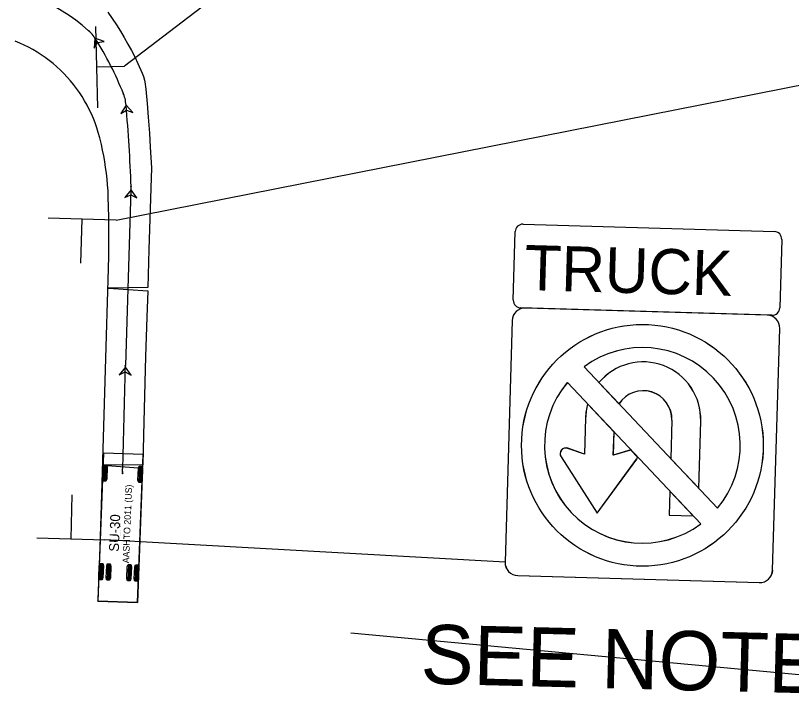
# Model space of a CAD drawing. Extents: x 2096670 to 2098561, y 684033 to 689893.
# Drawn here: x 2097702.4 to 2097859.5, y 686753.6 to 686892.9 of the extents above; entities that cross this region are included whole.
import ezdxf

# ---------------------------------------------------------------- set-up
doc = ezdxf.new("R2010")
doc.units = 0
for name, color, linetype in [('Exist Sign E No U Turn CELL', 7, 'Continuous'), ('Exist Sign E Two Direction', 7, 'Continuous'), ('Exist Support 1', 7, 'Continuous'), ('Old_Level_63', 7, 'Continuous'), ('Prop DSN Text', 7, 'Continuous'), ('Prop Sign E One Way_Right CELL', 7, 'Continuous'), ('Prop Sign E Signal Light Ahead CELL', 7, 'Continuous'), ('Scratch_Level_3', 7, 'Continuous')]:
    doc.layers.add(name, color=color, linetype=linetype)

# ---------------------------------------------------------------- blocks, each defined once
blk = doc.blocks.new('Exist No U Turn')
at = {"layer": 'Exist Sign E No U Turn CELL'}
for p, q in [((56.27, 62.3), (-56.61, 62.3)), ((-62.66, 56.26), (-62.66, -56.62)), ((62.31, -56.62), (62.31, 56.26)), ((-28.46, 35.7), (35.71, -28.46)), ((-28.46, 35.7), (-28.46, 35.7)), ((-36.06, 28.1), (28.11, -36.06)), ((-36.06, 28.1), (-36.06, 28.1)), ((-21.29, 28.54), (-11.65, 18.9)), ((-21.29, 28.54), (-11.65, 18.9)), ((-21.29, 28.54), (-11.65, 18.9)), ((-11.65, 18.9), (-11.65, 18.9)), ((-11.65, 18.9), (-11.65, 18.9)), ((-11.65, 18.9), (-11.65, 18.9)), ((-2.25, -5.71), (-5.43, -2.52)), ((-2.67, -6.68), (-2.67, -6.68)), ((-2.67, -6.68), (-2.67, -6.68)), ((-56.61, -62.67), (56.27, -62.67))]:
    blk.add_line(p, q, dxfattribs=at)
for points in [[(-2.25, -5.71), (-5.45, -2.51), (-13.61, -5.1), (-13.61, 5.66), (-26.27, 18.32)], [(-5.72, -2.6), (-13.61, -5.1), (-13.61, 5.66), (-26.27, 18.32)], [(-2.25, -5.71), (-5.45, -2.51), (-13.61, -5.1), (-13.61, 5.66), (-26.27, 18.32)], [(-27.05, 11.91), (-27.05, -5.1), (-34.96, -2.59)], [(-27.05, 11.91), (-27.05, -5.1), (-34.96, -2.59)], [(-27.05, 11.91), (-27.05, -5.1), (-34.96, -2.59)], [(13.27, 11.91), (13.27, -6.02), (26.7, -19.46), (26.7, 11.91)], [(13.27, 11.91), (13.27, -6.02), (26.7, -19.46), (26.7, 11.91)], [(13.27, 11.91), (13.27, -6.02), (26.7, -19.46), (26.7, 11.91)], [(-38, -6.67), (-20.33, -32.43), (-2.67, -6.68)], [(-38, -6.67), (-20.33, -32.43), (-2.67, -6.68)], [(-38, -6.67), (-20.33, -32.43), (-2.67, -6.68)]]:
    blk.add_lwpolyline(points, dxfattribs=at)
blk.add_lwpolyline([(13.27, -21.22), (13.27, -32.43), (24.48, -32.43)], close=True, dxfattribs=at)
blk.add_lwpolyline([(13.27, -21.22), (13.27, -32.43), (24.48, -32.43)], close=True, dxfattribs=at)
blk.add_lwpolyline([(13.27, -21.22), (13.27, -32.43), (24.48, -32.43)], close=True, dxfattribs=at)
blk.add_circle((-0.17, -0.18), 56.44, dxfattribs=at)
for centre, radius, start, end in [((-56.61, 56.26), 6.05, 90, 180), ((56.27, 56.26), 6.05, 0, 90), ((-0.17, -0.18), 45.69, 321.7553, 128.2447), ((-0.17, 11.91), 26.88, 359.9928, 141.788), ((-0.17, 11.91), 26.88, 359.9928, 141.788), ((-0.17, 11.91), 26.88, 359.9928, 141.788), ((-0.17, -0.18), 45.69, 141.7553, 308.2447), ((-0.17, 11.91), 13.44, 0, 148.6739), ((-0.17, 11.91), 13.44, 0, 148.6739), ((-0.17, 11.91), 13.44, 0, 148.6739), ((-0.17, 11.91), 26.87, 166.2094, 180), ((-0.17, 11.91), 26.87, 166.2094, 180), ((-0.17, 11.91), 26.87, 166.2094, 180), ((-35.78, -5.15), 2.69, 72.3746, 214.4704), ((-35.78, -5.15), 2.69, 72.3746, 214.4704), ((-35.78, -5.15), 2.69, 72.3746, 214.4704), ((-4.9, -5.14), 2.67, 101.5336, 108.0305), ((-4.9, -5.14), 2.67, 101.5336, 107.1991), ((-4.9, -5.14), 2.67, 101.5336, 107.1991), ((-4.88, -5.15), 2.69, 325.4527, 348.1626), ((-4.88, -5.15), 2.69, 325.4527, 348.1626), ((-4.88, -5.15), 2.69, 325.4527, 348.1626), ((-56.61, -56.62), 6.05, 180, 270), ((56.27, -56.62), 6.05, 270, 0)]:
    blk.add_arc(centre, radius, start, end, dxfattribs=at)

msp = doc.modelspace()

# ---------------------------------------------------------------- linework, layer by layer
at = {"layer": 'Exist Sign E No U Turn CELL'}
for p, q in [((2097805.19, 686850.68), (2097856.07, 686849.2)), ((2097803.2, 686835.31), (2097803.6, 686849.18)), ((2097857.57, 686847.61), (2097857.17, 686833.74)), ((2097855.58, 686832.24), (2097804.7, 686833.72)), ((2097854.6, 686832.27), (2097805.67, 686833.69)), ((2097802.97, 686831.15), (2097801.55, 686782.21)), ((2097855.73, 686780.64), (2097857.15, 686829.57)), ((2097817.54, 686821.8), (2097844.55, 686793.18)), ((2097817.54, 686821.8), (2097817.54, 686821.8)), ((2097814.15, 686818.6), (2097841.16, 686789.98)), ((2097814.15, 686818.6), (2097814.15, 686818.6)), ((2097820.56, 686818.61), (2097824.61, 686814.31)), ((2097820.56, 686818.61), (2097824.61, 686814.31)), ((2097820.56, 686818.61), (2097824.61, 686814.31)), ((2097824.61, 686814.31), (2097824.61, 686814.31)), ((2097824.61, 686814.31), (2097824.61, 686814.31)), ((2097824.61, 686814.31), (2097824.61, 686814.31)), ((2097828.38, 686803.52), (2097827.04, 686804.94)), ((2097828.19, 686803.1), (2097828.19, 686803.1)), ((2097828.19, 686803.1), (2097828.19, 686803.1)), ((2097801.55, 686782.21), (2097720.47, 686786.74)), ((2097804.09, 686779.51), (2097853.03, 686778.09))]:
    msp.add_line(p, q, dxfattribs=at)
for points in [[(2097828.38, 686803.52), (2097827.03, 686804.95), (2097823.46, 686803.93), (2097823.6, 686808.59), (2097818.27, 686814.24)], [(2097826.91, 686804.91), (2097823.46, 686803.93), (2097823.6, 686808.59), (2097818.27, 686814.24)], [(2097828.38, 686803.52), (2097827.03, 686804.95), (2097823.46, 686803.93), (2097823.6, 686808.59), (2097818.27, 686814.24)], [(2097817.85, 686811.47), (2097817.64, 686804.09), (2097814.24, 686805.28)], [(2097817.85, 686811.47), (2097817.64, 686804.09), (2097814.24, 686805.28)], [(2097817.85, 686811.47), (2097817.64, 686804.09), (2097814.24, 686805.28)], [(2097835.33, 686810.96), (2097835.1, 686803.19), (2097840.76, 686797.2), (2097841.15, 686810.79)], [(2097835.33, 686810.96), (2097835.1, 686803.19), (2097840.76, 686797.2), (2097841.15, 686810.79)], [(2097835.33, 686810.96), (2097835.1, 686803.19), (2097840.76, 686797.2), (2097841.15, 686810.79)], [(2097812.87, 686803.55), (2097820.2, 686792.16), (2097828.19, 686803.1)], [(2097812.87, 686803.55), (2097820.2, 686792.16), (2097828.19, 686803.1)], [(2097812.87, 686803.55), (2097820.2, 686792.16), (2097828.19, 686803.1)]]:
    msp.add_lwpolyline(points, dxfattribs=at)
msp.add_lwpolyline([(2097834.91, 686796.6), (2097834.77, 686791.74), (2097839.63, 686791.6)], close=True, dxfattribs=at)
msp.add_lwpolyline([(2097834.91, 686796.6), (2097834.77, 686791.74), (2097839.63, 686791.6)], close=True, dxfattribs=at)
msp.add_lwpolyline([(2097834.91, 686796.6), (2097834.77, 686791.74), (2097839.63, 686791.6)], close=True, dxfattribs=at)
msp.add_circle((2097829.35, 686805.89), 24.48, dxfattribs=at)
for centre, radius, start, end in [((2097805.14, 686849.14), 1.54, 88.334, 178.3348), ((2097856.03, 686847.66), 1.54, 358.3348, 88.334), ((2097804.74, 686835.26), 1.54, 178.3348, 268.334), ((2097805.59, 686831.07), 2.62, 88.3348, 178.3348), ((2097855.62, 686833.78), 1.54, 268.334, 358.3348), ((2097854.53, 686829.65), 2.62, 358.3348, 88.3348), ((2097829.35, 686805.89), 19.82, 320.0901, 126.5795), ((2097829.5, 686811.13), 11.66, 358.3276, 140.1228), ((2097829.5, 686811.13), 11.66, 358.3276, 140.1228), ((2097829.5, 686811.13), 11.66, 358.3276, 140.1228), ((2097829.35, 686805.89), 19.82, 140.0901, 306.5795), ((2097829.5, 686811.13), 5.83, 358.3348, 147.0088), ((2097829.5, 686811.13), 5.83, 358.3348, 147.0088), ((2097829.5, 686811.13), 5.83, 358.3348, 147.0088), ((2097829.5, 686811.13), 11.66, 164.5443, 178.3348), ((2097829.5, 686811.13), 11.66, 164.5443, 178.3348), ((2097829.5, 686811.13), 11.66, 164.5443, 178.3348), ((2097813.85, 686804.18), 1.17, 70.7095, 212.8052), ((2097813.85, 686804.18), 1.17, 70.7095, 212.8052), ((2097813.85, 686804.18), 1.17, 70.7095, 212.8052), ((2097827.24, 686803.8), 1.16, 99.8684, 106.3653), ((2097827.24, 686803.8), 1.16, 99.8684, 105.534), ((2097827.24, 686803.8), 1.16, 99.8684, 105.534), ((2097827.25, 686803.79), 1.17, 323.7876, 346.4975), ((2097827.25, 686803.79), 1.17, 323.7876, 346.4975), ((2097827.25, 686803.79), 1.17, 323.7876, 346.4975), ((2097804.17, 686782.13), 2.62, 178.3348, 268.3348), ((2097853.11, 686780.71), 2.62, 268.3348, 358.3348)]:
    msp.add_arc(centre, radius, start, end, dxfattribs=at)
at = {"layer": 'Exist Sign E Two Direction'}
msp.add_line((2097796.91, 686938.1), (2097724.46, 686882.69), dxfattribs=at)
at = {"layer": 'Exist Support 1'}
for p, q in [((2097719.05, 686874.28), (2097718.68, 686890.73)), ((2097718.86, 686882.57), (2097724.46, 686882.69))]:
    msp.add_line(p, q, dxfattribs=at)
at = {"layer": 'Old_Level_63'}
for p, q in [((2097720.24, 686804.31), (2097719.1, 686774.34)), ((2097728.23, 686804.01), (2097720.24, 686804.31)), ((2097720.24, 686804.31), (2097720.24, 686804.31)), ((2097727.09, 686774.03), (2097728.23, 686804.01)), ((2097720.36, 686801.97), (2097720.23, 686798.64)), ((2097720.57, 686801.97), (2097720.44, 686798.64)), ((2097720.78, 686801.96), (2097720.65, 686798.63)), ((2097727.52, 686801.7), (2097727.39, 686798.37)), ((2097727.73, 686801.69), (2097727.6, 686798.36)), ((2097727.94, 686801.68), (2097727.81, 686798.35)), ((2097719.6, 686781.99), (2097719.47, 686778.66)), ((2097719.81, 686781.98), (2097719.68, 686778.65)), ((2097720.01, 686781.97), (2097719.89, 686778.64)), ((2097721.1, 686781.93), (2097720.97, 686778.6)), ((2097721.3, 686781.92), (2097721.18, 686778.59)), ((2097721.51, 686781.92), (2097721.39, 686778.58)), ((2097725.26, 686781.77), (2097725.13, 686778.44)), ((2097725.47, 686781.76), (2097725.34, 686778.43)), ((2097725.68, 686781.76), (2097725.55, 686778.43)), ((2097726.76, 686781.72), (2097726.63, 686778.38)), ((2097726.97, 686781.71), (2097726.84, 686778.38)), ((2097727.17, 686781.7), (2097727.05, 686778.37)), ((2097719.1, 686774.34), (2097727.09, 686774.03))]:
    msp.add_line(p, q, dxfattribs=at)
for points in [[(2097721.08, 686893.61), (2097721.97, 686892.34), (2097722.82, 686891.06), (2097723.63, 686889.78), (2097724.41, 686888.48), (2097725.15, 686887.18), (2097725.86, 686885.88), (2097726.53, 686884.56), (2097727.17, 686883.25), (2097728.07, 686881.26), (2097728.33, 686880.58), (2097728.53, 686879.88), (2097728.6, 686879.51), (2097728.77, 686878.02), (2097729.04, 686875.13), (2097729.27, 686872.36), (2097729.52, 686869.12), (2097729.7, 686866.28), (2097729.92, 686862.13), (2097729.4, 686845.53), (2097729.21, 686837.86), (2097721.21, 686837.74), (2097729.19, 686837.19), (2097728.97, 686831.86), (2097728.72, 686823.89), (2097728.48, 686813.26), (2097728.35, 686807.94), (2097728.16, 686801.96), (2097720.15, 686801.87), (2097728.13, 686801.3), (2097727.09, 686774.03), (2097719.1, 686774.34), (2097719.11, 686774.62), (2097719.11, 686774.62)], [(2097718.48, 686888.35), (2097718.3, 686888.63), (2097718.1, 686888.9), (2097717.9, 686889.16), (2097717.68, 686889.41), (2097717.44, 686889.65), (2097717.2, 686889.88)], [(2097718.48, 686888.35), (2097718.32, 686886.35), (2097719.02, 686887.51), (2097720.37, 686887.68), (2097718.48, 686888.35)], [(2097719.11, 686774.62), (2097719.51, 686785.3), (2097719.87, 686795.91), (2097720.82, 686828.12), (2097721.25, 686841.67), (2097721.29, 686844.28), (2097721.31, 686846.89), (2097721.31, 686849.5), (2097721.28, 686852.09), (2097721.19, 686856.23), (2097721.13, 686857.44), (2097721.05, 686858.63), (2097720.94, 686859.82), (2097720.81, 686861.01), (2097720.65, 686862.19), (2097720.47, 686863.36), (2097720.27, 686864.52), (2097720.04, 686865.66), (2097719.79, 686866.8), (2097719.44, 686868.2), (2097719.15, 686869.25), (2097718.85, 686870.23), (2097718.52, 686871.18), (2097718.16, 686872.11), (2097717.76, 686873.03), (2097717.33, 686873.93), (2097716.88, 686874.82), (2097716.39, 686875.69), (2097715.88, 686876.53), (2097715.33, 686877.36), (2097714.76, 686878.18), (2097714.15, 686878.96), (2097713.53, 686879.73), (2097712.87, 686880.48), (2097712.19, 686881.2), (2097711.48, 686881.9), (2097710.75, 686882.57), (2097710, 686883.22), (2097709.22, 686883.84), (2097708.43, 686884.43), (2097707.61, 686884.99), (2097706.78, 686885.53), (2097705.92, 686886.04), (2097705.05, 686886.51), (2097704.16, 686886.95), (2097703.26, 686887.37), (2097702.35, 686887.75)], [(2097724.78, 686874.79), (2097724.75, 686875.13), (2097724.7, 686875.46), (2097724.64, 686875.78), (2097724.57, 686876.11), (2097724.48, 686876.43), (2097724.38, 686876.75), (2097724.26, 686877.06)], [(2097724.78, 686874.79), (2097723.7, 686873.11), (2097724.86, 686873.8), (2097726.13, 686873.32), (2097724.78, 686874.79)], [(2097725.79, 686857.62), (2097725.8, 686857.95), (2097725.79, 686858.29)], [(2097725.79, 686857.62), (2097724.52, 686856.07), (2097725.75, 686856.62), (2097726.95, 686855.99), (2097725.79, 686857.62)], [(2097724.64, 686821.75), (2097724.64, 686822.08)], [(2097724.64, 686821.75), (2097723.39, 686820.18), (2097724.61, 686820.75), (2097725.82, 686820.13), (2097724.64, 686821.75)], [(2097724.09, 686800.16), (2097724.1, 686800.5)]]:
    msp.add_lwpolyline(points, dxfattribs=at)
for points in [[(2097718.48, 686888.35), (2097718.32, 686886.35), (2097719.02, 686887.51), (2097720.37, 686887.68)], [(2097724.78, 686874.79), (2097723.7, 686873.11), (2097724.86, 686873.8), (2097726.13, 686873.32)], [(2097725.79, 686857.62), (2097724.52, 686856.07), (2097725.75, 686856.62), (2097726.95, 686855.99)], [(2097724.64, 686821.75), (2097723.39, 686820.18), (2097724.61, 686820.75), (2097725.82, 686820.13)], [(2097720.31, 686801.98), (2097720.83, 686801.96), (2097720.97, 686801.48), (2097720.88, 686799.09), (2097720.7, 686798.63), (2097720.18, 686798.65), (2097720.04, 686799.12), (2097720.13, 686801.52)], [(2097727.47, 686801.7), (2097727.99, 686801.68), (2097728.13, 686801.21), (2097728.04, 686798.81), (2097727.86, 686798.35), (2097727.34, 686798.37), (2097727.2, 686798.84), (2097727.3, 686801.24)], [(2097719.55, 686781.99), (2097720.06, 686781.97), (2097720.2, 686781.5), (2097720.11, 686779.1), (2097719.94, 686778.64), (2097719.42, 686778.66), (2097719.28, 686779.13), (2097719.37, 686781.53)], [(2097721.04, 686781.93), (2097721.56, 686781.91), (2097721.7, 686781.44), (2097721.61, 686779.04), (2097721.44, 686778.58), (2097720.92, 686778.6), (2097720.78, 686779.07), (2097720.87, 686781.47)], [(2097725.21, 686781.77), (2097725.73, 686781.75), (2097725.87, 686781.28), (2097725.77, 686778.88), (2097725.6, 686778.42), (2097725.08, 686778.44), (2097724.94, 686778.92), (2097725.03, 686781.31)], [(2097726.71, 686781.72), (2097727.23, 686781.7), (2097727.37, 686781.23), (2097727.27, 686778.83), (2097727.1, 686778.37), (2097726.58, 686778.39), (2097726.44, 686778.86), (2097726.53, 686781.26)]]:
    msp.add_lwpolyline(points, close=True, dxfattribs=at)
for centre in [(2097717.2, 686889.88), (2097717.2, 686889.88), (2097718.48, 686888.35), (2097718.48, 686888.35), (2097724.26, 686877.06), (2097724.26, 686877.06), (2097724.78, 686874.79), (2097724.78, 686874.79), (2097725.79, 686858.29), (2097725.79, 686858.29), (2097725.79, 686857.62), (2097725.79, 686857.62), (2097724.64, 686822.08), (2097724.64, 686822.08), (2097724.64, 686821.75), (2097724.64, 686821.75), (2097724.09, 686800.16), (2097724.1, 686800.5), (2097724.1, 686800.5)]:
    msp.add_circle(centre, 0.0417, dxfattribs=at)
for centre, radius, start, end in [((2097691.92, 686861.49), 38.01, 48.3146, 126.7544), ((2097666.17, 686854.43), 62.34, 21.2846, 32.9602), ((2097421.57, 686847.79), 304.41, 1.9764, 5.0898), ((2111460.24, 686397.81), 13742.15, 178.082555, 178.230815), ((2095342.48, 686871.4), 2382.67, 358.29465, 358.80576)]:
    msp.add_arc(centre, radius, start, end, dxfattribs=at)
at = {"layer": 'Prop DSN Text'}
for p, q in [((2097722.77, 686851.48), (2097709.01, 686851.88)), ((2097715.84, 686851.68), (2097715.58, 686842.76)), ((2097713.64, 686786.93), (2097713.9, 686795.85)), ((2097706.7, 686787.14), (2097720.47, 686786.74))]:
    msp.add_line(p, q, dxfattribs=at)
at = {"layer": 'Prop Sign E One Way_Right CELL'}
msp.add_line((2097722.77, 686851.48), (2097911.04, 686888.71), dxfattribs=at)
at = {"layer": 'Prop Sign E Signal Light Ahead CELL'}
for p, q in [((2097805.19, 686850.68), (2097856.07, 686849.2)), ((2097803.2, 686835.31), (2097803.6, 686849.18)), ((2097857.57, 686847.61), (2097857.17, 686833.74)), ((2097855.58, 686832.24), (2097804.7, 686833.72)), ((2097854.6, 686832.27), (2097805.67, 686833.69)), ((2097802.97, 686831.15), (2097801.55, 686782.21)), ((2097855.73, 686780.64), (2097857.15, 686829.57)), ((2097817.54, 686821.8), (2097844.55, 686793.18)), ((2097817.54, 686821.8), (2097817.54, 686821.8)), ((2097814.15, 686818.6), (2097841.16, 686789.98)), ((2097814.15, 686818.6), (2097814.15, 686818.6)), ((2097820.56, 686818.61), (2097824.61, 686814.31)), ((2097820.56, 686818.61), (2097824.61, 686814.31)), ((2097820.56, 686818.61), (2097824.61, 686814.31)), ((2097824.61, 686814.31), (2097824.61, 686814.31)), ((2097824.61, 686814.31), (2097824.61, 686814.31)), ((2097824.61, 686814.31), (2097824.61, 686814.31)), ((2097828.38, 686803.52), (2097827.04, 686804.94)), ((2097828.19, 686803.1), (2097828.19, 686803.1)), ((2097828.19, 686803.1), (2097828.19, 686803.1)), ((2097804.09, 686779.51), (2097853.03, 686778.09))]:
    msp.add_line(p, q, dxfattribs=at)
for points in [[(2097828.38, 686803.52), (2097827.03, 686804.95), (2097823.46, 686803.93), (2097823.6, 686808.59), (2097818.27, 686814.24)], [(2097826.91, 686804.91), (2097823.46, 686803.93), (2097823.6, 686808.59), (2097818.27, 686814.24)], [(2097828.38, 686803.52), (2097827.03, 686804.95), (2097823.46, 686803.93), (2097823.6, 686808.59), (2097818.27, 686814.24)], [(2097817.85, 686811.47), (2097817.64, 686804.09), (2097814.24, 686805.28)], [(2097817.85, 686811.47), (2097817.64, 686804.09), (2097814.24, 686805.28)], [(2097817.85, 686811.47), (2097817.64, 686804.09), (2097814.24, 686805.28)], [(2097835.33, 686810.96), (2097835.1, 686803.19), (2097840.76, 686797.2), (2097841.15, 686810.79)], [(2097835.33, 686810.96), (2097835.1, 686803.19), (2097840.76, 686797.2), (2097841.15, 686810.79)], [(2097835.33, 686810.96), (2097835.1, 686803.19), (2097840.76, 686797.2), (2097841.15, 686810.79)], [(2097812.87, 686803.55), (2097820.2, 686792.16), (2097828.19, 686803.1)], [(2097812.87, 686803.55), (2097820.2, 686792.16), (2097828.19, 686803.1)], [(2097812.87, 686803.55), (2097820.2, 686792.16), (2097828.19, 686803.1)]]:
    msp.add_lwpolyline(points, dxfattribs=at)
msp.add_lwpolyline([(2097834.91, 686796.6), (2097834.77, 686791.74), (2097839.63, 686791.6)], close=True, dxfattribs=at)
msp.add_lwpolyline([(2097834.91, 686796.6), (2097834.77, 686791.74), (2097839.63, 686791.6)], close=True, dxfattribs=at)
msp.add_lwpolyline([(2097834.91, 686796.6), (2097834.77, 686791.74), (2097839.63, 686791.6)], close=True, dxfattribs=at)
msp.add_circle((2097829.35, 686805.89), 24.48, dxfattribs=at)
for centre, radius, start, end in [((2097805.14, 686849.14), 1.54, 88.334, 178.3348), ((2097856.03, 686847.66), 1.54, 358.3348, 88.334), ((2097804.74, 686835.26), 1.54, 178.3348, 268.334), ((2097805.59, 686831.07), 2.62, 88.3348, 178.3348), ((2097855.62, 686833.78), 1.54, 268.334, 358.3348), ((2097854.53, 686829.65), 2.62, 358.3348, 88.3348), ((2097829.35, 686805.89), 19.82, 320.0901, 126.5795), ((2097829.5, 686811.13), 11.66, 358.3276, 140.1228), ((2097829.5, 686811.13), 11.66, 358.3276, 140.1228), ((2097829.5, 686811.13), 11.66, 358.3276, 140.1228), ((2097829.35, 686805.89), 19.82, 140.0901, 306.5795), ((2097829.5, 686811.13), 5.83, 358.3348, 147.0088), ((2097829.5, 686811.13), 5.83, 358.3348, 147.0088), ((2097829.5, 686811.13), 5.83, 358.3348, 147.0088), ((2097829.5, 686811.13), 11.66, 164.5443, 178.3348), ((2097829.5, 686811.13), 11.66, 164.5443, 178.3348), ((2097829.5, 686811.13), 11.66, 164.5443, 178.3348), ((2097813.85, 686804.18), 1.17, 70.7095, 212.8052), ((2097813.85, 686804.18), 1.17, 70.7095, 212.8052), ((2097813.85, 686804.18), 1.17, 70.7095, 212.8052), ((2097827.24, 686803.8), 1.16, 99.8684, 106.3653), ((2097827.24, 686803.8), 1.16, 99.8684, 105.534), ((2097827.24, 686803.8), 1.16, 99.8684, 105.534), ((2097827.25, 686803.79), 1.17, 323.7876, 346.4975), ((2097827.25, 686803.79), 1.17, 323.7876, 346.4975), ((2097827.25, 686803.79), 1.17, 323.7876, 346.4975), ((2097804.17, 686782.13), 2.62, 178.3348, 268.3348), ((2097853.11, 686780.71), 2.62, 268.3348, 358.3348)]:
    msp.add_arc(centre, radius, start, end, dxfattribs=at)
at = {"layer": 'Scratch_Level_3'}
msp.add_line((2097923.78, 686753.61), (2097770.28, 686767.84), dxfattribs=at)

# ---------------------------------------------------------------- block references
at = {"layer": 'Exist Sign E No U Turn CELL', "xscale": 0.4337086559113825, "yscale": 0.4337086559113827, "rotation": -1.665170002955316}
msp.add_blockref('Exist No U Turn', (2097829.43, 686805.97), dxfattribs=at)
at = {"layer": 'Prop Sign E Signal Light Ahead CELL', "xscale": 0.4337086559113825, "yscale": 0.4337086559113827, "rotation": -1.665170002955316}
msp.add_blockref('Exist No U Turn', (2097829.43, 686805.97), dxfattribs=at)

# ---------------------------------------------------------------- texts
at = {"layer": 'Exist Sign E No U Turn CELL'}
msp.add_text('TRUCK', height=9.136, rotation=358.3571, dxfattribs=at).set_placement((2097805.36, 686837.36))
at = {"layer": 'Old_Level_63'}
for s, height, p in [('AASHTO 2011 (US)', 1.3333, (2097725.4, 686781.98)), ('SU-30', 2, (2097723.32, 686784.32)), ('(c) 2022 Transoft Solutions, Inc. All rights reserved.', 0.08, (2097723.64, 686787.53))]:
    msp.add_text(s, height=height, rotation=87.8137, dxfattribs=at).set_placement(p)
at = {"layer": 'Prop DSN Text'}
msp.add_text('SEE NOTE 1', height=12, rotation=358.5578, dxfattribs=at).set_placement((2097784.36, 686757.65))
at = {"layer": 'Prop Sign E Signal Light Ahead CELL'}
msp.add_text('TRUCK', height=9.136, rotation=358.3571, dxfattribs=at).set_placement((2097805.36, 686837.36))

doc.saveas('drawing.dxf')
